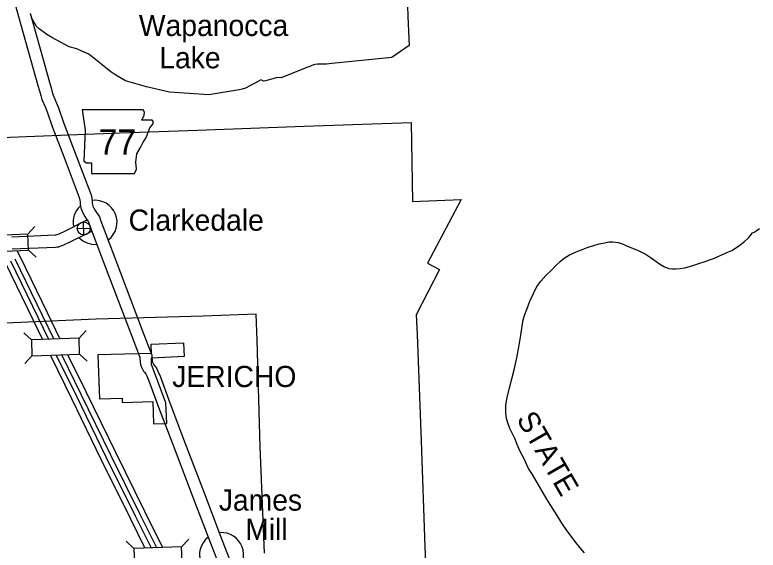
# Model space of a CAD drawing. Extents: x -117616 to 64730, y 54117 to 789866.
# Drawn here: x 61921.6 to 62107.1, y 55504.1 to 55637.7 of the extents above; entities that cross this region are included whole.
import ezdxf

# ---------------------------------------------------------------- set-up
doc = ezdxf.new("R2010")
doc.units = 0
for name, color, linetype in [('10', 7, 'Continuous'), ('19', 7, 'Continuous'), ('20', 7, 'Continuous'), ('21', 7, 'Continuous'), ('24', 7, 'Continuous'), ('26', 7, 'Continuous'), ('3', 7, 'Continuous'), ('6', 7, 'Continuous'), ('8', 7, 'Continuous'), ('9', 7, 'Continuous')]:
    doc.layers.add(name, color=color, linetype=linetype)

msp = doc.modelspace()

# ---------------------------------------------------------------- linework, layer by layer
at = {"layer": '10'}
for points in [[(61917.8, 55653.96), (61922.49, 55637.37), (61927.31, 55620.15), (61927.71, 55618.75), (61928.03, 55617.59), (61928.33, 55616.64), (61929.18, 55614.64), (61929.6, 55613.5), (61930.85, 55609.85), (61933.84, 55602.11), (61937.62, 55592.14), (61937.74, 55591.85), (61937.76, 55591.64), (61937.83, 55590.96), (61937.88, 55590.41), (61938.02, 55589.59), (61938.27, 55588.9), (61938.6, 55588.17), (61939.02, 55587.41), (61939.44, 55586.72), (61939.87, 55586.13), (61939.91, 55586.07), (61940.1, 55585.49), (61943.71, 55575.98), (61950.56, 55557.94), (61952.58, 55552.67), (61952.74, 55552.33), (61952.77, 55552.26), (61952.78, 55552.09), (61952.84, 55551.03), (61952.93, 55550.47), (61953.1, 55549.99), (61953.39, 55549.29), (61953.71, 55548.77), (61953.92, 55548.53), (61954.29, 55548.02), (61954.3, 55548), (61954.47, 55547.6), (61955.02, 55546.38), (61957.45, 55539.82), (61960.89, 55530.71), (61966.01, 55517.35), (61970.12, 55506.51), (61974.45, 55495.37)], [(61925.38, 55638.18), (61930.19, 55620.97), (61930.59, 55619.56), (61930.9, 55618.45), (61931.15, 55617.69), (61931.97, 55615.74), (61932.43, 55614.5), (61933.67, 55610.88), (61936.64, 55603.18), (61940.41, 55593.25), (61940.7, 55592.56), (61940.75, 55591.91), (61940.82, 55591.25), (61940.86, 55590.8), (61940.93, 55590.36), (61941.05, 55590.02), (61941.28, 55589.52), (61941.62, 55588.92), (61941.94, 55588.38), (61942.32, 55587.85), (61942.53, 55587.55), (61942.66, 55587.31), (61942.93, 55586.49), (61946.52, 55577.05), (61953.36, 55559.01), (61955.34, 55553.85), (61955.51, 55553.49), (61955.53, 55553.43), (61955.67, 55553.12), (61955.75, 55552.67), (61955.78, 55552.26), (61955.82, 55551.36), (61955.85, 55551.22), (61955.9, 55551.06), (61956.06, 55550.67), (61956.13, 55550.56), (61956.28, 55550.39), (61956.68, 55549.84), (61956.92, 55549.54), (61957.23, 55548.79), (61957.8, 55547.51), (61960.26, 55540.87), (61963.69, 55531.78), (61968.81, 55518.41), (61972.92, 55507.58), (61977.25, 55496.43)], [(61920.77, 55582.36), (61931.65, 55582.79), (61931.79, 55582.8), (61931.83, 55582.8), (61931.88, 55582.82), (61932.33, 55582.99), (61932.59, 55583.09), (61933.12, 55583.36), (61933.53, 55583.5), (61939.46, 55586.47), (61939.54, 55586.5)], [(61920.89, 55579.36), (61931.75, 55579.79), (61932.05, 55579.8), (61932.51, 55579.87), (61932.88, 55579.99), (61933.38, 55580.18), (61933.79, 55580.33), (61934.28, 55580.59), (61934.68, 55580.72), (61940.74, 55583.76), (61940.78, 55583.77)]]:
    msp.add_lwpolyline(points, dxfattribs=at)
at = {"layer": '19'}
for points in [[(61922.08, 55578.93), (61922.79, 55577.49)], [(61921.57, 55576.87), (61928.38, 55562.81), (61931.33, 55556.79)], [(61922.8, 55577.47), (61929.62, 55563.41), (61932.82, 55556.86)], [(61919.2, 55575.72), (61926.02, 55561.66), (61928.45, 55556.7)], [(61920.44, 55576.32), (61927.26, 55562.26), (61929.96, 55556.75)], [(61931.91, 55552.75), (61936.91, 55542.54), (61944.3, 55527.4), (61951.58, 55512.71), (61955.55, 55504.7)], [(61933.29, 55552.78), (61938.03, 55543.09), (61945.42, 55527.95), (61952.7, 55513.27), (61956.91, 55504.76)], [(61934.8, 55552.82), (61939.27, 55543.69), (61946.65, 55528.56), (61953.93, 55513.88), (61958.45, 55504.77)], [(61930.42, 55552.67), (61935.67, 55541.94), (61943.06, 55526.8), (61950.34, 55512.1), (61954.04, 55504.65)]]:
    msp.add_lwpolyline(points, dxfattribs=at)
at = {"layer": '20'}
for p, q in [((61924.77, 55582.97), (61926.55, 55584.92)), ((61924.94, 55579.02), (61926.88, 55577.23)), ((61925.71, 55556.6), (61923.77, 55558.4)), ((61937.58, 55557.02), (61939.38, 55558.95)), ((61937.72, 55553.06), (61939.65, 55551.26)), ((61925.84, 55552.65), (61924.04, 55550.72)), ((61951.28, 55504.54), (61949.34, 55506.34)), ((61963.15, 55504.95), (61964.95, 55506.89))]:
    msp.add_line(p, q, dxfattribs=at)
for points in [[(61913.07, 55578.51), (61924.94, 55579.02), (61924.77, 55582.97), (61912.9, 55582.46)], [(61937.58, 55557.02), (61925.71, 55556.6), (61925.84, 55552.65), (61937.72, 55553.06)], [(61963.15, 55504.95), (61951.28, 55504.54), (61951.41, 55500.58), (61963.29, 55501)]]:
    msp.add_lwpolyline(points, close=True, dxfattribs=at)
at = {"layer": '21'}
msp.add_lwpolyline([(61938.36, 55614.03), (61939.12, 55608.95), (61938.78, 55601.25), (61939.46, 55600.83), (61940.73, 55600.83), (61940.73, 55598.12), (61951.39, 55598.12), (61951.89, 55599.22), (61951.73, 55601), (61951.98, 55603.03), (61952.91, 55604.64), (61953.5, 55605.82), (61954.35, 55607.09), (61954.85, 55608.44), (61955.28, 55609.54), (61956.04, 55610.47), (61956.21, 55611.07), (61955.87, 55611.49), (61953.25, 55611.49), (61953.84, 55612.67), (61953.92, 55613.43), (61953.57, 55614.02)], close=True, dxfattribs=at)
at = {"layer": '24'}
for centre, start, end in [((61941.58, 55585.95), 132.3575, 190.4915), ((61941.58, 55585.95), 306.9539, 97.1772), ((61941.58, 55585.95), 224.1186, 273.3665), ((61973.16, 55503), 307.5429, 93.7585), ((61973.16, 55503), 129.0531, 273.7586)]:
    msp.add_arc(centre, 5.5, start, end, dxfattribs=at)
at = {"layer": '26'}
for p, q in [((61937.13, 55584.41), (61940.39, 55584.48)), ((61938.8, 55582.82), (61938.72, 55586.07))]:
    msp.add_line(p, q, dxfattribs=at)
msp.add_circle((61938.76, 55584.44), 1.63, dxfattribs=at)
at = {"layer": '3'}
for points in [[(62088.72, 55574.57), (62090.3, 55574.99), (62092.26, 55575.66), (62093.86, 55576.18), (62095, 55576.56), (62096.19, 55577.04), (62097.49, 55577.62), (62099.71, 55578.56), (62100.56, 55578.96), (62101.43, 55579.47), (62102.32, 55580.08), (62102.94, 55580.55), (62103.78, 55581.27), (62104.53, 55581.92), (62104.82, 55582.21), (62105.73, 55583.33), (62106.1, 55583.52), (62106.59, 55583.84), (62107.45, 55584.44)], [(62063.76, 55503.47), (62062.7, 55504.68), (62061.6, 55505.99), (62060.43, 55507.57), (62059.35, 55509.03), (62058.14, 55510.81), (62057.33, 55512.09), (62054.35, 55516.84), (62050.77, 55523.01), (62049.82, 55524.51), (62049.36, 55525.45), (62048.67, 55526.87), (62047.65, 55528.89), (62046.95, 55530.52), (62046.41, 55531.84), (62045.84, 55533.01), (62045.15, 55534.51), (62044.6, 55535.91), (62044.25, 55537.01), (62044.13, 55538.38), (62044.15, 55540.3), (62044.44, 55542.2), (62045.03, 55544.66), (62045.58, 55546.88), (62046.2, 55549.09), (62046.85, 55552.15), (62047.42, 55555.29), (62047.85, 55557.76), (62048.2, 55560.07), (62048.48, 55561.62), (62048.88, 55562.98), (62049.43, 55564.47), (62050.07, 55566.28), (62051, 55568.19), (62051.89, 55569.91), (62052.84, 55571.29), (62054.11, 55572.69), (62055.51, 55574.03), (62056.63, 55575.19), (62057.66, 55576.2), (62058.7, 55577.02), (62060.05, 55577.81), (62062.11, 55578.77), (62063.45, 55579.28), (62064.7, 55579.73), (62066.07, 55580.19), (62067.4, 55580.57), (62068.79, 55580.86), (62069.82, 55581.08), (62070.83, 55581.11), (62072.13, 55580.88), (62073.39, 55580.5), (62074.26, 55580.12), (62075.74, 55579.48), (62077.14, 55578.9), (62077.99, 55578.53), (62078.86, 55578.1), (62080.17, 55577.25), (62081.35, 55576.39), (62082.71, 55575.44), (62083.72, 55574.86), (62084.81, 55574.46), (62085.73, 55574.33), (62086.53, 55574.31), (62087.64, 55574.39), (62088.72, 55574.57)]]:
    msp.add_lwpolyline(points, dxfattribs=at)
at = {"layer": '6'}
for points in [[(61913.9, 55606.97), (61926.58, 55607.48), (61947.82, 55608.3), (61967.19, 55608.92), (61993.82, 55609.93), (62020.51, 55610.87), (62020.79, 55591.15), (62032.96, 55591.63), (62024.6, 55575.74), (62027.6, 55574.16), (62021.75, 55562.88), (62021.98, 55557.91), (62022.95, 55531.44), (62023.86, 55504.92), (62024.45, 55491.74)], [(61983.91, 55503.4), (61982.8, 55529.92), (61982.09, 55556.5), (61981.84, 55563.04), (61968.58, 55562.53), (61941.9, 55561.8), (61915.44, 55560.62)], [(61963.78, 55555.82), (61955.53, 55555.46), (61955.61, 55553.18), (61942.25, 55552.87), (61942.67, 55541.88)], [(61942.67, 55541.88), (61948.31, 55542.05), (61948.35, 55540.96), (61955.99, 55541.19), (61956.17, 55535.64), (61959.47, 55535.75), (61959.29, 55540.88), (61955.69, 55550.43), (61955.64, 55552.16), (61963.88, 55552.52), (61963.78, 55555.82)]]:
    msp.add_lwpolyline(points, dxfattribs=at)
at = {"layer": '8'}
msp.add_lwpolyline([(62018.81, 55664.04), (62019.63, 55637.36), (62019.99, 55630.11), (62015.65, 55627.07), (62000.68, 55625.57), (61999.37, 55625.42), (61998.86, 55625.41), (61998.17, 55625.4), (61997.58, 55625.43), (61997.1, 55625.42), (61996.55, 55625.39), (61996.19, 55625.29), (61995.7, 55625.09), (61995.19, 55624.88), (61994.41, 55624.6), (61988.01, 55622.05), (61987.12, 55622.07), (61984.16, 55621.24), (61983.6, 55621.16), (61983.08, 55621.5), (61980.4, 55620.08), (61979.1, 55619.48), (61978.3, 55619.22), (61977.54, 55619.01), (61969.99, 55617.81), (61960.18, 55618.41), (61954.43, 55619.75), (61949.17, 55621.26), (61946.73, 55622.7), (61945.51, 55623.53), (61943.34, 55625.29), (61940, 55627.97), (61938.29, 55628.68), (61937.06, 55629.24), (61935.15, 55629.79), (61933.11, 55630.82), (61930.8, 55632.07), (61929.54, 55632.83), (61927.59, 55634.23), (61926.92, 55634.95), (61926.61, 55635.48), (61926.3, 55635.93), (61925.96, 55636.65), (61925.92, 55636.78)], dxfattribs=at)

# ---------------------------------------------------------------- texts
at = {"layer": '21'}
msp.add_text('77', height=6.336, dxfattribs=at).set_placement((61942.44, 55602.84))
at = {"layer": '24'}
for s, p in [('Clarkedale', (61949.96, 55583.86)), ('James', (61972.47, 55513.98)), ('Mill', (61979.07, 55506.69))]:
    msp.add_text(s, height=5.28, dxfattribs=at).set_placement(p)
at = {"layer": '3'}
msp.add_text('STATE', height=5.28, rotation=300, dxfattribs=at).set_placement((62046.65, 55536.85))
at = {"layer": '6'}
msp.add_text('JERICHO', height=5.28, dxfattribs=at).set_placement((61960.84, 55544.83))
at = {"layer": '9'}
for s, p in [('Wapanocca', (61952.52, 55632.46)), ('Lake', (61957.61, 55624.4))]:
    msp.add_text(s, height=5.28, dxfattribs=at).set_placement(p)

doc.saveas('drawing.dxf')
